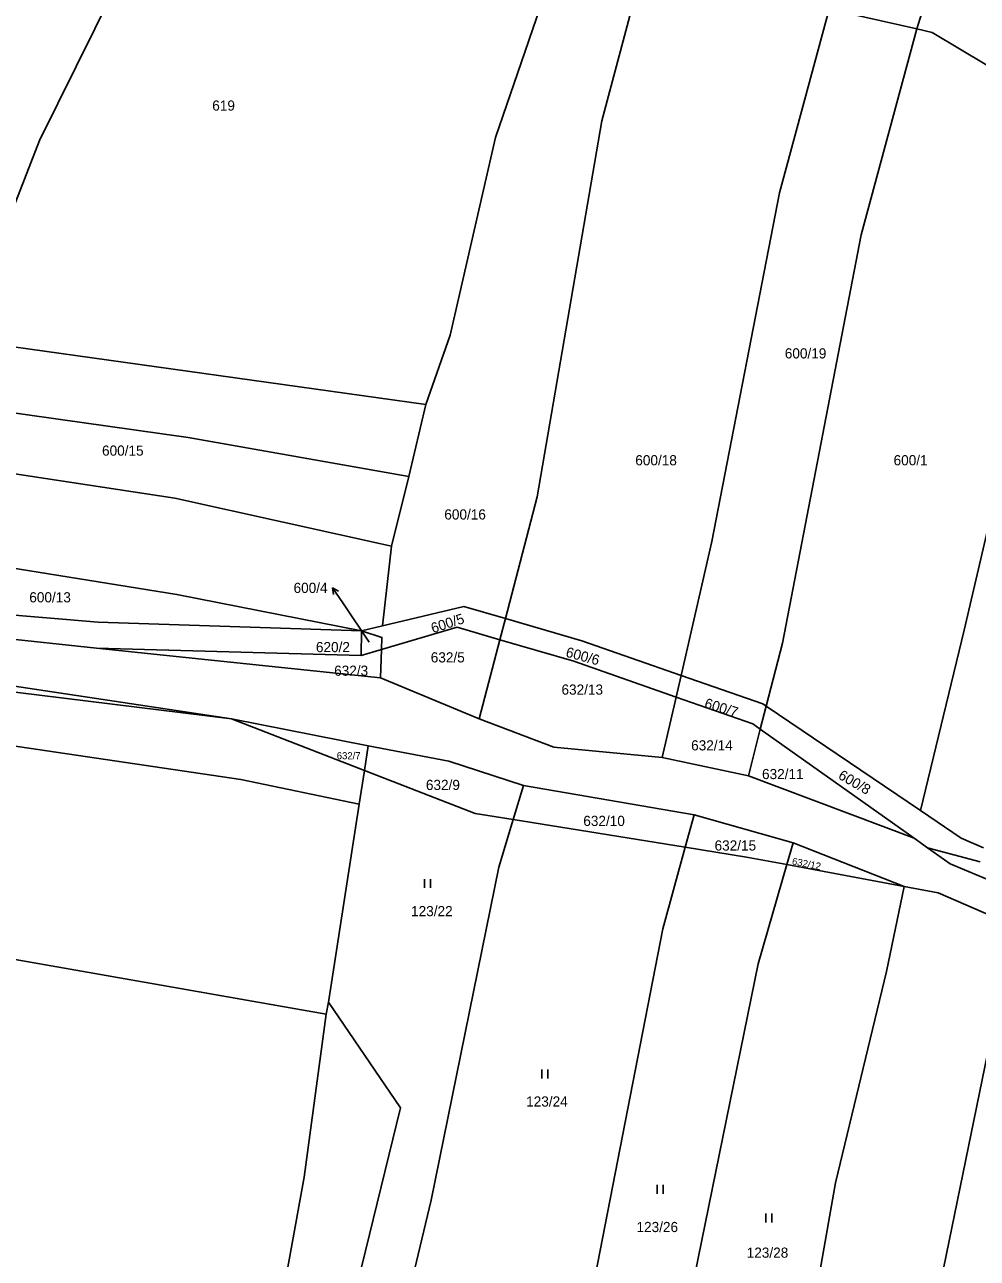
# Model space of a CAD drawing. Extents: x -746176 to -739709, y -1128407 to -1124482.
# Drawn here: x -742633.6 to -742474.2, y -1127345.9 to -1127139.5 of the extents above; entities that cross this region are included whole.
import ezdxf

# ---------------------------------------------------------------- set-up
doc = ezdxf.new("R2010")
doc.units = 0
for name, color, linetype in [('Vrstva 33', 7, 'Continuous'), ('Vrstva 42', 7, 'Continuous'), ('Vrstva 43', 7, 'Continuous'), ('Vrstva 44', 7, 'Continuous')]:
    doc.layers.add(name, color=color, linetype=linetype)

msp = doc.modelspace()

# ---------------------------------------------------------------- linework, layer by layer
at = {"layer": 'Vrstva 33'}
for p, q in [((-742477.79, -1127119.09), (-742484.3, -1127140.22)), ((-742498.96, -1127136.92), (-742484.3, -1127140.22)), ((-742566.48, -1127203.04), (-742644.1, -1127192.22)), ((-742569.32, -1127215.09), (-742566.48, -1127203.04)), ((-742572.17, -1127226.73), (-742569.32, -1127215.09)), ((-742573.72, -1127240.07), (-742572.17, -1127226.73)), ((-742554.07, -1127242.4), (-742553.15, -1127238.87)), ((-742639.2, -1127241.9), (-742621.56, -1127243.8)), ((-742577.26, -1127245.05), (-742577.19, -1127240.89)), ((-742573.72, -1127240.07), (-742577.19, -1127240.89)), ((-742678.76, -1127243.56), (-742598.97, -1127255.65)), ((-742621.56, -1127243.8), (-742574.02, -1127248.78)), ((-742621.56, -1127243.8), (-742577.26, -1127245.05)), ((-742577.26, -1127245.05), (-742573.86, -1127244.05)), ((-742574.02, -1127248.78), (-742573.86, -1127244.05)), ((-742557.53, -1127255.65), (-742554.07, -1127242.4)), ((-742574.02, -1127248.78), (-742557.53, -1127255.65)), ((-742524.58, -1127252.01), (-742523.75, -1127248.38)), ((-742526.9, -1127262.12), (-742524.58, -1127252.01)), ((-742510.5, -1127257.39), (-742509.51, -1127253.53)), ((-742509.51, -1127253.53), (-742483.68, -1127270.99)), ((-742576.08, -1127260.13), (-742598.97, -1127255.65)), ((-742576.72, -1127264.27), (-742598.97, -1127255.65)), ((-742510.5, -1127257.39), (-742512.49, -1127265.17)), ((-742510.5, -1127257.39), (-742484.78, -1127275.57)), ((-742576.72, -1127264.27), (-742576.08, -1127260.13)), ((-742526.9, -1127262.12), (-742512.49, -1127265.17)), ((-742577.59, -1127269.9), (-742576.72, -1127264.27)), ((-742551.83, -1127272.48), (-742550.1, -1127266.78)), ((-742521.55, -1127271.68), (-742550.1, -1127266.78)), ((-742512.49, -1127265.17), (-742484.78, -1127275.57)), ((-742582.72, -1127303.04), (-742577.59, -1127269.9)), ((-742523.05, -1127277.11), (-742551.83, -1127272.48)), ((-742523.05, -1127277.11), (-742521.55, -1127271.68)), ((-742504.98, -1127276.38), (-742521.55, -1127271.68)), ((-742504.98, -1127276.38), (-742506.04, -1127280.03)), ((-742486.41, -1127283.7), (-742504.98, -1127276.38)), ((-742484.78, -1127275.57), (-742482.5, -1127277.19)), ((-742473.74, -1127279.57), (-742482.5, -1127277.19)), ((-742486.41, -1127283.7), (-742506.04, -1127280.03)), ((-742583.12, -1127305.02), (-742582.72, -1127303.04))]:
    msp.add_line(p, q, dxfattribs=at)
for points in [[(-742644.1, -1127192.22), (-742631.06, -1127158.9), (-742603.37, -1127102.87)], [(-742543.65, -1127125.88), (-742554.78, -1127158.4), (-742562.37, -1127191.45), (-742566.48, -1127203.04)], [(-742553.15, -1127238.87), (-742547.82, -1127218.47), (-742536.99, -1127155.61), (-742532.11, -1127137.2)], [(-742523.75, -1127248.38), (-742518.59, -1127225.94), (-742507.29, -1127167.65), (-742498.96, -1127136.92)], [(-742484.3, -1127140.22), (-742493.61, -1127174.67), (-742506.81, -1127242.95), (-742509.51, -1127253.53)], [(-742454.04, -1127157.35), (-742481.72, -1127140.8), (-742484.3, -1127140.22)], [(-742483.68, -1127270.99), (-742476.39, -1127240.81), (-742460.54, -1127173), (-742454.04, -1127157.35)], [(-742725.69, -1127194.04), (-742650.94, -1127202.29), (-742606.23, -1127208.56), (-742569.32, -1127215.09)], [(-742572.17, -1127226.73), (-742608.43, -1127218.73), (-742647.39, -1127212.79), (-742690.57, -1127207.86)], [(-742664.96, -1127226.26), (-742655.98, -1127227.12), (-742608.13, -1127234.85), (-742577.19, -1127240.89)], [(-742577.19, -1127240.89), (-742621.26, -1127239.44), (-742638.6, -1127238), (-742659.14, -1127230.44), (-742664.96, -1127226.26)], [(-742553.15, -1127238.87), (-742560.09, -1127236.86), (-742573.72, -1127240.07)], [(-742523.75, -1127248.38), (-742540.33, -1127242.59), (-742553.15, -1127238.87)], [(-742573.86, -1127244.05), (-742573.79, -1127242.02), (-742577.19, -1127240.89)], [(-742573.86, -1127244.05), (-742561.22, -1127240.32), (-742554.07, -1127242.4)], [(-742598.97, -1127255.65), (-742642.9, -1127250.2), (-742660.81, -1127251.7), (-742678.76, -1127243.56)], [(-742554.07, -1127242.4), (-742541.7, -1127246.01), (-742524.58, -1127252.01)], [(-742736.14, -1127250.3), (-742715.39, -1127251.55), (-742655.59, -1127257.18), (-742597.39, -1127265.81), (-742577.59, -1127269.9)], [(-742509.51, -1127253.53), (-742510.08, -1127253.15), (-742523.75, -1127248.38)], [(-742524.58, -1127252.01), (-742511.77, -1127256.49), (-742510.5, -1127257.39)], [(-742557.53, -1127255.65), (-742545.05, -1127260.38), (-742526.9, -1127262.12)], [(-742550.1, -1127266.78), (-742562.63, -1127262.7), (-742576.08, -1127260.13)], [(-742551.83, -1127272.48), (-742558.2, -1127271.45), (-742576.72, -1127264.27)], [(-742473.15, -1127277.19), (-742476.88, -1127275.58), (-742483.68, -1127270.99)], [(-742571.73, -1127362.05), (-742565.58, -1127336.15), (-742554.25, -1127280.44), (-742551.83, -1127272.48)], [(-742543.19, -1127372.64), (-742538.11, -1127348.86), (-742526.83, -1127290.76), (-742523.05, -1127277.11)], [(-742506.04, -1127280.03), (-742512.81, -1127278.76), (-742523.05, -1127277.11)], [(-742482.5, -1127277.19), (-742478.71, -1127279.87), (-742435.6, -1127297.95), (-742390.76, -1127324.91), (-742338.36, -1127352.64), (-742294.93, -1127366.2), (-742262.34, -1127370.73), (-742214.62, -1127379.37), (-742176.91, -1127386.35)], [(-742530.91, -1127395.09), (-742510.84, -1127296.63), (-742506.04, -1127280.03)], [(-742583.12, -1127305.02), (-742639.33, -1127295.15), (-742725.03, -1127283.28)], [(-742511.41, -1127409.84), (-742497.94, -1127333.24), (-742489.37, -1127297.91), (-742486.41, -1127283.7)], [(-742467.25, -1127290.58), (-742480.76, -1127284.76), (-742486.41, -1127283.7)], [(-742492.74, -1127410.43), (-742471.55, -1127307.03), (-742467.25, -1127290.58)], [(-742582.72, -1127303.04), (-742570.71, -1127320.74), (-742580.44, -1127360.6), (-742571.73, -1127362.05)], [(-742593.77, -1127370.76), (-742586.78, -1127332.31), (-742583.12, -1127305.02)]]:
    msp.add_lwpolyline(points, dxfattribs=at)
at = {"layer": 'Vrstva 43'}
for p, q in [((-742580.36, -1127236.21), (-742582.04, -1127233.72)), ((-742582.04, -1127233.72), (-742581.06, -1127234.27)), ((-742582.04, -1127233.72), (-742581.89, -1127234.83)), ((-742575.92, -1127242.8), (-742580.36, -1127236.21))]:
    msp.add_line(p, q, dxfattribs=at)
at = {"layer": 'Vrstva 44'}
for p, q in [((-742566.69, -1127283.93), (-742566.69, -1127282.43)), ((-742565.69, -1127283.93), (-742565.69, -1127282.43)), ((-742547.04, -1127315.8), (-742547.04, -1127314.3)), ((-742546.04, -1127315.8), (-742546.04, -1127314.3)), ((-742527.75, -1127335.11), (-742527.75, -1127333.61)), ((-742526.75, -1127335.11), (-742526.75, -1127333.61)), ((-742509.55, -1127339.91), (-742509.55, -1127338.41)), ((-742508.55, -1127339.91), (-742508.55, -1127338.41))]:
    msp.add_line(p, q, dxfattribs=at)

# ---------------------------------------------------------------- texts
at = {"layer": 'Vrstva 42'}
for s, height, p in [('619', 1.7, (-742602.18, -1127153.88)), ('600/19', 1.7, (-742506.4, -1127195.34)), ('600/15', 1.7, (-742620.62, -1127211.61)), ('600/18', 1.7, (-742531.41, -1127213.22)), ('600/1', 1.7, (-742488.2, -1127213.22)), ('600/16', 1.7, (-742563.36, -1127222.29)), ('600/4', 1.7, (-742588.58, -1127234.57)), ('600/13', 1.7, (-742632.79, -1127236.15)), ('620/2', 1.7, (-742584.84, -1127244.48)), ('632/5', 1.7, (-742565.63, -1127246.2)), ('632/3', 1.7, (-742581.79, -1127248.43)), ('632/13', 1.7, (-742543.76, -1127251.59)), ('632/14', 1.7, (-742522.07, -1127260.92)), ('632/7', 1.19, (-742581.35, -1127262.4)), ('632/11', 1.7, (-742510.21, -1127265.72)), ('632/9', 1.7, (-742566.44, -1127267.54)), ('632/10', 1.7, (-742540.11, -1127273.56)), ('632/15', 1.7, (-742518.15, -1127277.67)), ('123/22', 1.7, (-742568.92, -1127288.65)), ('123/24', 1.7, (-742549.67, -1127320.5)), ('123/26', 1.7, (-742531.21, -1127341.5)), ('123/28', 1.7, (-742512.77, -1127345.79))]:
    msp.add_text(s, height=height, dxfattribs=at).set_placement(p)
for s, height, rotation, p in [('600/5', 1.7, 18, (-742565.27, -1127241.33)), ('600/6', 1.7, 345, (-742543.16, -1127245.22)), ('600/7', 1.7, 343, (-742519.97, -1127253.75)), ('600/8', 1.7, 330, (-742497.6, -1127265.55)), ('632/12', 1.19, 349, (-742505.27, -1127280))]:
    msp.add_text(s, height=height, rotation=rotation, dxfattribs=at).set_placement(p)

doc.saveas('drawing.dxf')
